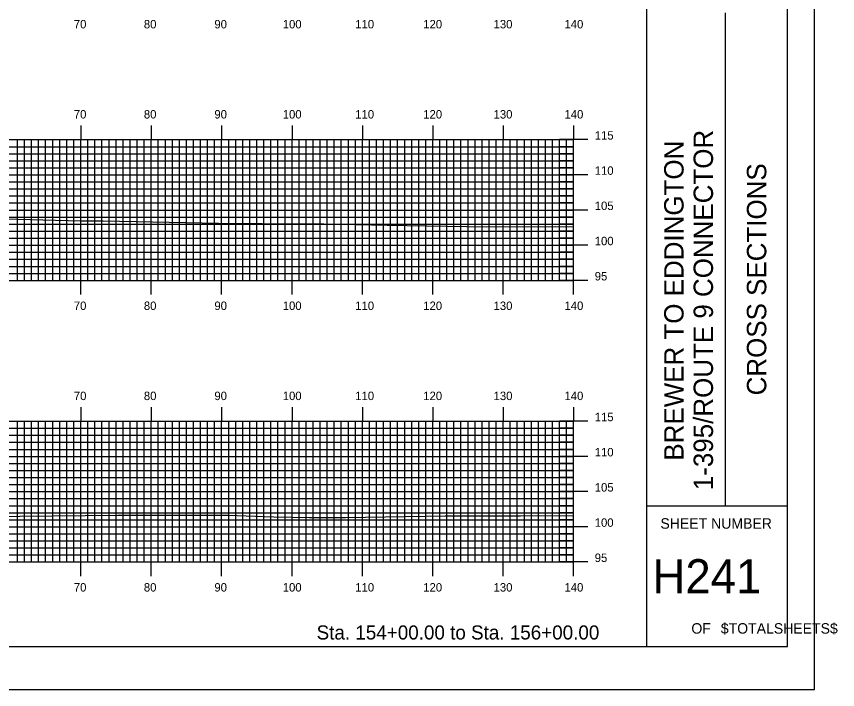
# Model space of a CAD drawing. Extents: x 1779106 to 1779449, y 442591 to 442811.
# Drawn here: x 1779332.2 to 1779448.8, y 442590.5 to 442686.2 of the extents above; entities that cross this region are included whole.
import ezdxf

# ---------------------------------------------------------------- set-up
doc = ezdxf.new("R2010")
doc.units = 0
for name, color, linetype in [('BORDER', 7, 'Continuous'), ('H_V ANNOTATION', 7, 'Continuous'), ('MAJOR', 7, 'Continuous'), ('MINOR', 7, 'Continuous'), ('PLOT BOUNDARY', 7, 'Continuous'), ('S_Roadway_Centerline', 7, 'Continuous')]:
    doc.layers.add(name, color=color, linetype=linetype)

msp = doc.modelspace()

# ---------------------------------------------------------------- linework, layer by layer
at = {"layer": 'BORDER'}
for p, q in [((1779421.73, 442596.67), (1779421.73, 442806.67)), ((1779432.91, 442616.67), (1779432.91, 442686.67)), ((1779421.73, 442616.67), (1779441.73, 442616.67))]:
    msp.add_line(p, q, dxfattribs=at)
msp.add_lwpolyline([(1779121.73, 442596.67), (1779441.73, 442596.67), (1779441.73, 442806.67), (1779121.73, 442806.67)], close=True, dxfattribs=at)
at = {"layer": 'MAJOR'}
for p, q in [((1779341.33, 442670.67), (1779341.33, 442668.67)), ((1779351.33, 442670.67), (1779351.33, 442668.67)), ((1779361.33, 442670.67), (1779361.33, 442668.67)), ((1779371.33, 442670.67), (1779371.33, 442668.67)), ((1779381.33, 442670.67), (1779381.33, 442668.67)), ((1779391.33, 442670.67), (1779391.33, 442668.67)), ((1779401.33, 442670.67), (1779401.33, 442668.67)), ((1779411.33, 442670.67), (1779411.33, 442668.67)), ((1779131.33, 442668.67), (1779411.33, 442668.67)), ((1779131.33, 442668.67), (1779411.33, 442668.67)), ((1779341.33, 442648.67), (1779341.33, 442668.67)), ((1779351.33, 442648.67), (1779351.33, 442668.67)), ((1779361.33, 442648.67), (1779361.33, 442668.67)), ((1779371.33, 442648.67), (1779371.33, 442668.67)), ((1779381.33, 442648.67), (1779381.33, 442668.67)), ((1779391.33, 442648.67), (1779391.33, 442668.67)), ((1779401.33, 442648.67), (1779401.33, 442668.67)), ((1779413.33, 442668.67), (1779409.33, 442668.67)), ((1779411.33, 442648.67), (1779411.33, 442668.67)), ((1779411.33, 442648.67), (1779411.33, 442668.67)), ((1779131.33, 442663.67), (1779411.33, 442663.67)), ((1779413.33, 442663.67), (1779409.33, 442663.67)), ((1779131.33, 442658.67), (1779411.33, 442658.67)), ((1779413.33, 442658.67), (1779409.33, 442658.67)), ((1779131.33, 442653.67), (1779411.33, 442653.67)), ((1779413.33, 442653.67), (1779409.33, 442653.67)), ((1779131.33, 442648.67), (1779411.33, 442648.67)), ((1779131.33, 442648.67), (1779411.33, 442648.67)), ((1779341.33, 442646.66), (1779341.33, 442648.67)), ((1779351.33, 442646.66), (1779351.33, 442648.67)), ((1779361.33, 442646.66), (1779361.33, 442648.67)), ((1779371.33, 442646.66), (1779371.33, 442648.67)), ((1779381.33, 442646.66), (1779381.33, 442648.67)), ((1779391.33, 442646.66), (1779391.33, 442648.67)), ((1779401.33, 442646.66), (1779401.33, 442648.67)), ((1779413.33, 442648.67), (1779409.33, 442648.67)), ((1779411.33, 442646.66), (1779411.33, 442648.67)), ((1779341.33, 442630.67), (1779341.33, 442628.67)), ((1779351.33, 442630.67), (1779351.33, 442628.67)), ((1779361.33, 442630.67), (1779361.33, 442628.67)), ((1779371.33, 442630.67), (1779371.33, 442628.67)), ((1779381.33, 442630.67), (1779381.33, 442628.67)), ((1779391.33, 442630.67), (1779391.33, 442628.67)), ((1779401.33, 442630.67), (1779401.33, 442628.67)), ((1779411.33, 442630.67), (1779411.33, 442628.67)), ((1779131.33, 442628.67), (1779411.33, 442628.67)), ((1779131.33, 442628.67), (1779411.33, 442628.67)), ((1779341.33, 442608.67), (1779341.33, 442628.67)), ((1779351.33, 442608.67), (1779351.33, 442628.67)), ((1779361.33, 442608.67), (1779361.33, 442628.67)), ((1779371.33, 442608.67), (1779371.33, 442628.67)), ((1779381.33, 442608.67), (1779381.33, 442628.67)), ((1779391.33, 442608.67), (1779391.33, 442628.67)), ((1779401.33, 442608.67), (1779401.33, 442628.67)), ((1779413.33, 442628.67), (1779409.33, 442628.67)), ((1779411.33, 442608.67), (1779411.33, 442628.67)), ((1779411.33, 442608.67), (1779411.33, 442628.67)), ((1779131.33, 442623.67), (1779411.33, 442623.67)), ((1779413.33, 442623.67), (1779409.33, 442623.67)), ((1779131.33, 442618.67), (1779411.33, 442618.67)), ((1779413.33, 442618.67), (1779409.33, 442618.67)), ((1779131.33, 442613.67), (1779411.33, 442613.67)), ((1779413.33, 442613.67), (1779409.33, 442613.67)), ((1779131.33, 442608.67), (1779411.33, 442608.67)), ((1779131.33, 442608.67), (1779411.33, 442608.67)), ((1779341.33, 442606.66), (1779341.33, 442608.67)), ((1779351.33, 442606.66), (1779351.33, 442608.67)), ((1779361.33, 442606.66), (1779361.33, 442608.67)), ((1779371.33, 442606.66), (1779371.33, 442608.67)), ((1779381.33, 442606.66), (1779381.33, 442608.67)), ((1779391.33, 442606.66), (1779391.33, 442608.67)), ((1779401.33, 442606.66), (1779401.33, 442608.67)), ((1779413.33, 442608.67), (1779409.33, 442608.67)), ((1779411.33, 442606.66), (1779411.33, 442608.67))]:
    msp.add_line(p, q, dxfattribs=at)
at = {"layer": 'MINOR'}
for p, q in [((1779332.33, 442648.67), (1779332.33, 442668.67)), ((1779333.33, 442648.67), (1779333.33, 442668.67)), ((1779334.33, 442648.67), (1779334.33, 442668.67)), ((1779335.33, 442648.67), (1779335.33, 442668.67)), ((1779336.33, 442648.67), (1779336.33, 442668.67)), ((1779337.33, 442648.67), (1779337.33, 442668.67)), ((1779338.33, 442648.67), (1779338.33, 442668.67)), ((1779339.33, 442648.67), (1779339.33, 442668.67)), ((1779340.33, 442648.67), (1779340.33, 442668.67)), ((1779342.33, 442648.67), (1779342.33, 442668.67)), ((1779343.33, 442648.67), (1779343.33, 442668.67)), ((1779344.33, 442648.67), (1779344.33, 442668.67)), ((1779345.33, 442648.67), (1779345.33, 442668.67)), ((1779346.33, 442648.67), (1779346.33, 442668.67)), ((1779347.33, 442648.67), (1779347.33, 442668.67)), ((1779348.33, 442648.67), (1779348.33, 442668.67)), ((1779349.33, 442648.67), (1779349.33, 442668.67)), ((1779350.33, 442648.67), (1779350.33, 442668.67)), ((1779352.33, 442648.67), (1779352.33, 442668.67)), ((1779353.33, 442648.67), (1779353.33, 442668.67)), ((1779354.33, 442648.67), (1779354.33, 442668.67)), ((1779355.33, 442648.67), (1779355.33, 442668.67)), ((1779356.33, 442648.67), (1779356.33, 442668.67)), ((1779357.33, 442648.67), (1779357.33, 442668.67)), ((1779358.33, 442648.67), (1779358.33, 442668.67)), ((1779359.33, 442648.67), (1779359.33, 442668.67)), ((1779360.33, 442648.67), (1779360.33, 442668.67)), ((1779362.33, 442648.67), (1779362.33, 442668.67)), ((1779363.33, 442648.67), (1779363.33, 442668.67)), ((1779364.33, 442648.67), (1779364.33, 442668.67)), ((1779365.33, 442648.67), (1779365.33, 442668.67)), ((1779366.33, 442648.67), (1779366.33, 442668.67)), ((1779367.33, 442648.67), (1779367.33, 442668.67)), ((1779368.33, 442648.67), (1779368.33, 442668.67)), ((1779369.33, 442648.67), (1779369.33, 442668.67)), ((1779370.33, 442648.67), (1779370.33, 442668.67)), ((1779372.33, 442648.67), (1779372.33, 442668.67)), ((1779373.33, 442648.67), (1779373.33, 442668.67)), ((1779374.33, 442648.67), (1779374.33, 442668.67)), ((1779375.33, 442648.67), (1779375.33, 442668.67)), ((1779376.33, 442648.67), (1779376.33, 442668.67)), ((1779377.33, 442648.67), (1779377.33, 442668.67)), ((1779378.33, 442648.67), (1779378.33, 442668.67)), ((1779379.33, 442648.67), (1779379.33, 442668.67)), ((1779380.33, 442648.67), (1779380.33, 442668.67)), ((1779382.33, 442648.67), (1779382.33, 442668.67)), ((1779383.33, 442648.67), (1779383.33, 442668.67)), ((1779384.33, 442648.67), (1779384.33, 442668.67)), ((1779385.33, 442648.67), (1779385.33, 442668.67)), ((1779386.33, 442648.67), (1779386.33, 442668.67)), ((1779387.33, 442648.67), (1779387.33, 442668.67)), ((1779388.33, 442648.67), (1779388.33, 442668.67)), ((1779389.33, 442648.67), (1779389.33, 442668.67)), ((1779390.33, 442648.67), (1779390.33, 442668.67)), ((1779392.33, 442648.67), (1779392.33, 442668.67)), ((1779393.33, 442648.67), (1779393.33, 442668.67)), ((1779394.33, 442648.67), (1779394.33, 442668.67)), ((1779395.33, 442648.67), (1779395.33, 442668.67)), ((1779396.33, 442648.67), (1779396.33, 442668.67)), ((1779397.33, 442648.67), (1779397.33, 442668.67)), ((1779398.33, 442648.67), (1779398.33, 442668.67)), ((1779399.33, 442648.67), (1779399.33, 442668.67)), ((1779400.33, 442648.67), (1779400.33, 442668.67)), ((1779402.33, 442648.67), (1779402.33, 442668.67)), ((1779403.33, 442648.67), (1779403.33, 442668.67)), ((1779404.33, 442648.67), (1779404.33, 442668.67)), ((1779405.33, 442648.67), (1779405.33, 442668.67)), ((1779406.33, 442648.67), (1779406.33, 442668.67)), ((1779407.33, 442648.67), (1779407.33, 442668.67)), ((1779408.33, 442648.67), (1779408.33, 442668.67)), ((1779409.33, 442648.67), (1779409.33, 442668.67)), ((1779410.33, 442648.67), (1779410.33, 442668.67)), ((1779131.33, 442667.67), (1779411.33, 442667.67)), ((1779411.33, 442667.67), (1779409.33, 442667.67)), ((1779131.33, 442666.67), (1779411.33, 442666.67)), ((1779411.33, 442666.67), (1779409.33, 442666.67)), ((1779131.33, 442665.67), (1779411.33, 442665.67)), ((1779411.33, 442665.67), (1779409.33, 442665.67)), ((1779131.33, 442664.67), (1779411.33, 442664.67)), ((1779411.33, 442664.67), (1779409.33, 442664.67)), ((1779131.33, 442662.67), (1779411.33, 442662.67)), ((1779411.33, 442662.67), (1779409.33, 442662.67)), ((1779131.33, 442661.67), (1779411.33, 442661.67)), ((1779411.33, 442661.67), (1779409.33, 442661.67)), ((1779131.33, 442660.67), (1779411.33, 442660.67)), ((1779411.33, 442660.67), (1779409.33, 442660.67)), ((1779131.33, 442659.67), (1779411.33, 442659.67)), ((1779411.33, 442659.67), (1779409.33, 442659.67)), ((1779131.33, 442657.67), (1779411.33, 442657.67)), ((1779131.33, 442656.67), (1779411.33, 442656.67)), ((1779411.33, 442657.67), (1779409.33, 442657.67)), ((1779411.33, 442656.67), (1779409.33, 442656.67)), ((1779131.33, 442655.67), (1779411.33, 442655.67)), ((1779411.33, 442655.67), (1779409.33, 442655.67)), ((1779131.33, 442654.67), (1779411.33, 442654.67)), ((1779411.33, 442654.67), (1779409.33, 442654.67)), ((1779131.33, 442652.67), (1779411.33, 442652.67)), ((1779411.33, 442652.67), (1779409.33, 442652.67)), ((1779131.33, 442651.67), (1779411.33, 442651.67)), ((1779411.33, 442651.67), (1779409.33, 442651.67)), ((1779131.33, 442650.67), (1779411.33, 442650.67)), ((1779131.33, 442649.67), (1779411.33, 442649.67)), ((1779411.33, 442650.67), (1779409.33, 442650.67)), ((1779411.33, 442649.67), (1779409.33, 442649.67)), ((1779332.33, 442608.67), (1779332.33, 442628.67)), ((1779333.33, 442608.67), (1779333.33, 442628.67)), ((1779334.33, 442608.67), (1779334.33, 442628.67)), ((1779335.33, 442608.67), (1779335.33, 442628.67)), ((1779336.33, 442608.67), (1779336.33, 442628.67)), ((1779337.33, 442608.67), (1779337.33, 442628.67)), ((1779338.33, 442608.67), (1779338.33, 442628.67)), ((1779339.33, 442608.67), (1779339.33, 442628.67)), ((1779340.33, 442608.67), (1779340.33, 442628.67)), ((1779342.33, 442608.67), (1779342.33, 442628.67)), ((1779343.33, 442608.67), (1779343.33, 442628.67)), ((1779344.33, 442608.67), (1779344.33, 442628.67)), ((1779345.33, 442608.67), (1779345.33, 442628.67)), ((1779346.33, 442608.67), (1779346.33, 442628.67)), ((1779347.33, 442608.67), (1779347.33, 442628.67)), ((1779348.33, 442608.67), (1779348.33, 442628.67)), ((1779349.33, 442608.67), (1779349.33, 442628.67)), ((1779350.33, 442608.67), (1779350.33, 442628.67)), ((1779352.33, 442608.67), (1779352.33, 442628.67)), ((1779353.33, 442608.67), (1779353.33, 442628.67)), ((1779354.33, 442608.67), (1779354.33, 442628.67)), ((1779355.33, 442608.67), (1779355.33, 442628.67)), ((1779356.33, 442608.67), (1779356.33, 442628.67)), ((1779357.33, 442608.67), (1779357.33, 442628.67)), ((1779358.33, 442608.67), (1779358.33, 442628.67)), ((1779359.33, 442608.67), (1779359.33, 442628.67)), ((1779360.33, 442608.67), (1779360.33, 442628.67)), ((1779362.33, 442608.67), (1779362.33, 442628.67)), ((1779363.33, 442608.67), (1779363.33, 442628.67)), ((1779364.33, 442608.67), (1779364.33, 442628.67)), ((1779365.33, 442608.67), (1779365.33, 442628.67)), ((1779366.33, 442608.67), (1779366.33, 442628.67)), ((1779367.33, 442608.67), (1779367.33, 442628.67)), ((1779368.33, 442608.67), (1779368.33, 442628.67)), ((1779369.33, 442608.67), (1779369.33, 442628.67)), ((1779370.33, 442608.67), (1779370.33, 442628.67)), ((1779372.33, 442608.67), (1779372.33, 442628.67)), ((1779373.33, 442608.67), (1779373.33, 442628.67)), ((1779374.33, 442608.67), (1779374.33, 442628.67)), ((1779375.33, 442608.67), (1779375.33, 442628.67)), ((1779376.33, 442608.67), (1779376.33, 442628.67)), ((1779377.33, 442608.67), (1779377.33, 442628.67)), ((1779378.33, 442608.67), (1779378.33, 442628.67)), ((1779379.33, 442608.67), (1779379.33, 442628.67)), ((1779380.33, 442608.67), (1779380.33, 442628.67)), ((1779382.33, 442608.67), (1779382.33, 442628.67)), ((1779383.33, 442608.67), (1779383.33, 442628.67)), ((1779384.33, 442608.67), (1779384.33, 442628.67)), ((1779385.33, 442608.67), (1779385.33, 442628.67)), ((1779386.33, 442608.67), (1779386.33, 442628.67)), ((1779387.33, 442608.67), (1779387.33, 442628.67)), ((1779388.33, 442608.67), (1779388.33, 442628.67)), ((1779389.33, 442608.67), (1779389.33, 442628.67)), ((1779390.33, 442608.67), (1779390.33, 442628.67)), ((1779392.33, 442608.67), (1779392.33, 442628.67)), ((1779393.33, 442608.67), (1779393.33, 442628.67)), ((1779394.33, 442608.67), (1779394.33, 442628.67)), ((1779395.33, 442608.67), (1779395.33, 442628.67)), ((1779396.33, 442608.67), (1779396.33, 442628.67)), ((1779397.33, 442608.67), (1779397.33, 442628.67)), ((1779398.33, 442608.67), (1779398.33, 442628.67)), ((1779399.33, 442608.67), (1779399.33, 442628.67)), ((1779400.33, 442608.67), (1779400.33, 442628.67)), ((1779402.33, 442608.67), (1779402.33, 442628.67)), ((1779403.33, 442608.67), (1779403.33, 442628.67)), ((1779404.33, 442608.67), (1779404.33, 442628.67)), ((1779405.33, 442608.67), (1779405.33, 442628.67)), ((1779406.33, 442608.67), (1779406.33, 442628.67)), ((1779407.33, 442608.67), (1779407.33, 442628.67)), ((1779408.33, 442608.67), (1779408.33, 442628.67)), ((1779409.33, 442608.67), (1779409.33, 442628.67)), ((1779410.33, 442608.67), (1779410.33, 442628.67)), ((1779131.33, 442627.67), (1779411.33, 442627.67)), ((1779411.33, 442627.67), (1779409.33, 442627.67)), ((1779131.33, 442626.67), (1779411.33, 442626.67)), ((1779411.33, 442626.67), (1779409.33, 442626.67)), ((1779131.33, 442625.67), (1779411.33, 442625.67)), ((1779411.33, 442625.67), (1779409.33, 442625.67)), ((1779131.33, 442624.67), (1779411.33, 442624.67)), ((1779411.33, 442624.67), (1779409.33, 442624.67)), ((1779131.33, 442622.67), (1779411.33, 442622.67)), ((1779131.33, 442621.67), (1779411.33, 442621.67)), ((1779411.33, 442622.67), (1779409.33, 442622.67)), ((1779411.33, 442621.67), (1779409.33, 442621.67)), ((1779131.33, 442620.67), (1779411.33, 442620.67)), ((1779411.33, 442620.67), (1779409.33, 442620.67)), ((1779131.33, 442619.67), (1779411.33, 442619.67)), ((1779411.33, 442619.67), (1779409.33, 442619.67)), ((1779131.33, 442617.67), (1779411.33, 442617.67)), ((1779411.33, 442617.67), (1779409.33, 442617.67)), ((1779131.33, 442616.67), (1779411.33, 442616.67)), ((1779411.33, 442616.67), (1779409.33, 442616.67)), ((1779131.33, 442615.67), (1779411.33, 442615.67)), ((1779131.33, 442614.67), (1779411.33, 442614.67)), ((1779411.33, 442615.67), (1779409.33, 442615.67)), ((1779411.33, 442614.67), (1779409.33, 442614.67)), ((1779131.33, 442612.67), (1779411.33, 442612.67)), ((1779411.33, 442612.67), (1779409.33, 442612.67)), ((1779131.33, 442611.67), (1779411.33, 442611.67)), ((1779411.33, 442611.67), (1779409.33, 442611.67)), ((1779131.33, 442610.67), (1779411.33, 442610.67)), ((1779411.33, 442610.67), (1779409.33, 442610.67)), ((1779131.33, 442609.67), (1779411.33, 442609.67)), ((1779411.33, 442609.67), (1779409.33, 442609.67))]:
    msp.add_line(p, q, dxfattribs=at)
at = {"layer": 'PLOT BOUNDARY'}
msp.add_lwpolyline([(1779105.54, 442590.55), (1779445.54, 442590.55), (1779445.54, 442810.55), (1779105.54, 442810.55)], close=True, dxfattribs=at)
at = {"layer": 'S_Roadway_Centerline'}
for points in [[(1779321.52, 442657.67), (1779341.31, 442657.13), (1779344.5, 442657.12), (1779360.86, 442656.79), (1779367.07, 442656.74), (1779375.86, 442656.73), (1779384.85, 442656.53), (1779398.89, 442656.28), (1779408.71, 442656.34), (1779411.33, 442656.28)], [(1779327.98, 442615.12), (1779346.56, 442615.33), (1779350.46, 442615.31), (1779354.96, 442615.33), (1779362.21, 442615.34), (1779368.76, 442615.09), (1779373.81, 442614.98), (1779378.92, 442615), (1779393.07, 442615.24), (1779403.79, 442615.24), (1779411.33, 442615.28)]]:
    msp.add_lwpolyline(points, dxfattribs=at)

# ---------------------------------------------------------------- texts
at = {"layer": 'BORDER'}
for s, p in [('1-395/ROUTE 9 CONNECTOR', (1779431.13, 442618.87)), ('BREWER TO EDDINGTON', (1779426.95, 442623.07)), ('CROSS SECTIONS', (1779438.7, 442632.34))]:
    msp.add_text(s, height=2.7557, rotation=90, dxfattribs=at).set_placement(p)
for s, height, p in [('SHEET NUMBER', 1.4905, (1779423.66, 442613.4)), ('H241', 4.839, (1779422.53, 442604.23)), ('OF', 1.491, (1779428.06, 442598.49)), ('$TOTALSHEETS$', 1.4905, (1779432.24, 442598.49))]:
    msp.add_text(s, height=height, dxfattribs=at).set_placement(p)
at = {"layer": 'H_V ANNOTATION'}
for s, height, p in [('70', 1.2, (1779340.33, 442684.47)), ('80', 1.2, (1779350.28, 442684.47)), ('90', 1.2, (1779360.3, 442684.47)), ('100', 1.2, (1779370.01, 442684.47)), ('110', 1.2, (1779380.31, 442684.47)), ('120', 1.2, (1779389.97, 442684.47)), ('130', 1.2, (1779399.96, 442684.47)), ('140', 1.2, (1779410.03, 442684.47)), ('70', 1.2, (1779340.33, 442671.67)), ('80', 1.2, (1779350.28, 442671.67)), ('90', 1.2, (1779360.3, 442671.67)), ('100', 1.2, (1779370.01, 442671.67)), ('110', 1.2, (1779380.31, 442671.67)), ('120', 1.2, (1779389.97, 442671.67)), ('130', 1.2, (1779399.96, 442671.67)), ('140', 1.2, (1779410.03, 442671.67)), ('115', 1.2, (1779414.33, 442668.67)), ('110', 1.2, (1779414.33, 442663.67)), ('105', 1.2, (1779414.33, 442658.67)), ('100', 1.2, (1779414.33, 442653.67)), ('95', 1.2, (1779414.33, 442648.67)), ('70', 1.2, (1779340.33, 442644.47)), ('80', 1.2, (1779350.28, 442644.47)), ('90', 1.2, (1779360.3, 442644.47)), ('100', 1.2, (1779370.01, 442644.47)), ('110', 1.2, (1779380.31, 442644.47)), ('120', 1.2, (1779389.97, 442644.47)), ('130', 1.2, (1779399.96, 442644.47)), ('140', 1.2, (1779410.03, 442644.47)), ('70', 1.2, (1779340.33, 442631.67)), ('80', 1.2, (1779350.28, 442631.67)), ('90', 1.2, (1779360.3, 442631.67)), ('100', 1.2, (1779370.01, 442631.67)), ('110', 1.2, (1779380.31, 442631.67)), ('120', 1.2, (1779389.97, 442631.67)), ('130', 1.2, (1779399.96, 442631.67)), ('140', 1.2, (1779410.03, 442631.67)), ('115', 1.2, (1779414.33, 442628.67)), ('110', 1.2, (1779414.33, 442623.67)), ('105', 1.2, (1779414.33, 442618.67)), ('100', 1.2, (1779414.33, 442613.67)), ('95', 1.2, (1779414.33, 442608.67)), ('70', 1.2, (1779340.33, 442604.47)), ('80', 1.2, (1779350.28, 442604.47)), ('90', 1.2, (1779360.3, 442604.47)), ('100', 1.2, (1779370.01, 442604.47)), ('110', 1.2, (1779380.31, 442604.47)), ('120', 1.2, (1779389.97, 442604.47)), ('130', 1.2, (1779399.96, 442604.47)), ('140', 1.2, (1779410.03, 442604.47)), ('Sta. 154+00.00 to Sta. 156+00.00', 2.0004, (1779374.82, 442597.66))]:
    msp.add_text(s, height=height, dxfattribs=at).set_placement(p)

doc.saveas('drawing.dxf')
